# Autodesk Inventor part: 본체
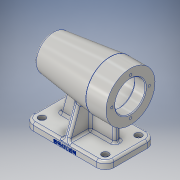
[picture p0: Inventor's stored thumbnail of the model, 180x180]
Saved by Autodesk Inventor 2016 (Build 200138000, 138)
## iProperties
Created: 2018-09
Part Number: 본체
Material: Aluminum 6061
Document SubType Name: Modeling
Designer: CAMTIC
Mass: 732.763 g
Surface Area: 663.623 cm^2
Volume: 271.394 cm^3
Density: 2.7 g/cm^3
Appearance: Aluminum - Flat
Author: CAMTIC
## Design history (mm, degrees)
sketch "Sketch1"
  geometry: L1 (56, -35)-(-56, -35); L2 (-56, -35)-(-56, 35); L3 (-56, 35)-(56, 35); L4 (56, 35)-(56, -35); L5 (0, -49)-(0, 49) reference; L6 (78.4, 0)-(-78.4, 0) reference; 3 further points
  constraints: 8 end point, 2 midpoint, 2 parallel, 2 point on line, 1 horizontal, 1 perpendicular
  dimensions: "d0" = 112 distance of L2.end L3.end; "d1" = 70 distance of L1.end L2.end
extrude "Extrusion1" new body sketch "Sketch1" distance "d2" = 10; taper "d3" = 0 deg
sketch "Sketch3"
  geometry: L1 (56, 108)-(56, 74); L2 (56, 74)-(-56, 74); L3 (56, 108)-(28, 108); L4 (28, 108)-(-52.27, 98.144); L5 (56, 0)-(56, 10) reference; A1 r 80 centre (24, 74) between (-52.27, 98.144) and (-56, 74); 1 further point
  constraints: 8 end point, 2 point on circle, 2 point on line, 1 centre point, 1 horizontal, 1 perpendicular, 1 vertical
  dimensions: "d4" = 160 diameter of A1; "d5" = 7 deg angle of L3 L4; "d6" = 28 distance of L1.start L3.end; "d7" = 112 distance of L2.end L1.end; "d8" = 74 distance from line of L2 point (0, 0); "d9" = 34 distance of L1.start L1.end
revolve "Revolution1" sketch "Sketch3" stored, may be unused: angle "d10" = 90 deg
sketch "Sketch4"
  geometry: L1 (-38, 10)-(-23.173, 65.333); L2 (56, 10)-(-56, 10) reference; L3 (-56, 0)-(-56, 10) reference; L4 (38, 10)-(38, 56.447); L5 (56, 0)-(56, 10) reference; L6 (-23.173, 65.333)-(38, 56.447); L7 (-38, 10)-(38, 10); 1 further point
  constraints: 8 end point, 2 point on line, 1 collinear, 1 vertical
  dimensions: "d12" = 105 deg angle of L2 L1; "d13" = 18 distance from line of L1.start L3; "d14" = 18 distance between parallel lines of L5 L4; "d15" = 46.44721 distance of L4.start L4.end; "d16" = 61.17345 horizontal distance of L1.end L4.end
extrude "Extrusion2" join sketch "Sketch4" stored distance "d17" = 8; taper "d18" = 0 deg
hole "Hole1" diameter "d26" = 42; stored, may be unused: countersink angle "d30" = 90 deg, drill point angle "d32" = 0 deg; dims "d24" = 10, "d25" = 10, "d27" = 6, "d28" = 4, "d29" = 2, "d31" = 15
hole "Hole2" diameter "d35" = 48; stored, may be unused: countersink angle "d39" = 90 deg, drill point angle "d41" = 0 deg; dims "d33" = 10, "d34" = 10, "d36" = 6, "d37" = 4, "d38" = 2, "d40" = 54
hole "Hole3" diameter "d44" = 42; stored, may be unused: countersink angle "d48" = 90 deg, drill point angle "d50" = 0 deg; dims "d42" = 10, "d43" = 10, "d45" = 6, "d46" = 4, "d47" = 2, "d49" = 12
hole "Hole4" diameter "d53" = 35; stored, may be unused: countersink angle "d57" = 90 deg, drill point angle "d59" = 0 deg; dims "d51" = 10, "d52" = 10, "d54" = 6, "d55" = 4, "d56" = 2, "d58" = 18
hole "Hole5" diameter "d62" = 32; stored, may be unused: countersink angle "d66" = 90 deg, drill point angle "d68" = 0 deg; dims "d60" = 10, "d61" = 10, "d63" = 6, "d64" = 4, "d65" = 2, "d67" = 4
hole "Hole6" diameter "d71" = 21; stored, may be unused: countersink angle "d75" = 90 deg, drill point angle "d77" = 0 deg; dims "d69" = 10, "d70" = 10, "d72" = 6, "d73" = 4, "d74" = 2, "d76" = 3
sketch "Sketch6"
  geometry: L1 (0, -95.6)-(0, 55.6) reference; C1 r 10.5 at (0, 0) reference; 2 further points
  constraints: 1 point on line
  dimensions: "d78" = 26 distance of C1.centre point (0, 26)
hole "Hole7" sketch "Sketch6" at (0, 26) diameter "d79" = 3.242; stored, may be unused: countersink angle "d83" = 90 deg, drill point angle "d85" = 118 deg; dims "d80" = 8, "d81" = 4, "d82" = 2, "d84" = 11
pattern_circular "Circular Pattern1" dims angle "d87" = 360 deg
fillet "Fillet1" dims "d89" = 12
fillet "Fillet2" dims "d90" = 0.3
fillet "Fillet3" dims "d91" = 3
fillet "Fillet4" dims "d92" = 3
sketch "Sketch9"
  geometry: L1 (50.889, 19.218)-(8.026, 34.819); L2 (3.022, 34.819)-(3.022, -34.819); L3 (8.026, -34.819)-(50.889, -19.218); L4 (0, 35)-(7, 35) reference; L5 (7, -35)-(0, -35) reference; L6 (-21.6, 0)-(129.6, 0) reference; L7 (10, 4)-(10, -4) reference; L8 (8.026, -34.819)-(3.022, -34.819); L9 (8.026, 34.819)-(3.022, 34.819); L10 (50.889, 19.218)-(44.709, 0); L11 (50.889, -19.218)-(44.709, 0); L12 (0, 23)-(0, -23) reference; A1 r 3 centre (7, 32) between (10, 32) and (7, 35) reference; A2 r 3 centre (7, -32) between (7, -35) and (10, -32) reference; 3 further points
  constraints: 14 end point, 3 point on line, 2 point on circle, 2 tangent, 1 horizontal, 1 midpoint, 1 parallel, 1 vertical
  dimensions: "d93" = 20 deg angle of L4 L1; "d94" = 20 deg angle of L5 L3; "d97" = 6.17925 horizontal distance of L1.start L10.end; "d98" = 92.1759 deg angle of L1 L10; "d99" = 92.1759 deg angle of L3 L11; "d100" = 3.02189 distance between parallel lines of L12 L2
extrude "Extrusion4" join sketch "Sketch9" stored distance "d101" = 8; taper "d102" = 0 deg
fillet "Fillet5" dims "d103" = 3
fillet "Fillet6" dims "d104" = 3
fillet "Fillet7" dims "d105" = 3
fillet "Fillet8" dims "d106" = 3
fillet "Fillet9" dims "d107" = 3
fillet "Fillet10" dims "d108" = 3
fillet "Fillet11" dims "d109" = 3
sketch "Sketch10"
  geometry: A1 r 9 centre (-44, 23) between (-44, 32) and (-53, 23) reference; A2 r 9 centre (-44, -23) between (-53, -23) and (-44, -32) reference; A3 r 9 centre (44, -23) between (44, -32) and (53, -23) reference; A4 r 9 centre (44, 23) between (53, 23) and (44, 32) reference; 5 further points
  constraints: 4 coincident
hole "Hole8" sketch "Sketch10" at (-44, 23), (-44, -23), (44, -23), (44, 23) diameter "d110" = 5.5; stored, may be unused: countersink angle "d114" = 90 deg, drill point angle "d116" = 0 deg; dims "d111" = 8, "d112" = 9.5, "d113" = 5.4, "d115" = 10
workplane "Work Plane1"
sketch "Sketch12"
  geometry: L1 (100, 0)-(100, 7) reference; L2 (44, 21.905)-(44, -2.148); L3 (44, 3)-(15.922, 3); 1 further point
  constraints: 4 end point, 1 horizontal, 1 point on line, 1 vertical, 1 other
  dimensions: "d120" = 3 distance of point (44, 0) L3.start; "d121" = 56 distance from line of L1 L3.start
emboss "Emboss1" sketch "Sketch12" dims "d0" = 112, "d1" = 70, "d122" = 0.5, "d123" = 0
chamfer "Chamfer1" distance "d125" = 1; stored, may be unused: second distance "d126" = 2, angle "d127" = 45 deg
body "Solid1"
other parameters: "d119" = 0.5
